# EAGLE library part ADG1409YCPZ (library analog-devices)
4 Ohm RON, 4-Channel, ±15 V/+12 V/±5 V iCMOS Multiplexers Source: 8x ADG1408_1409.pdf
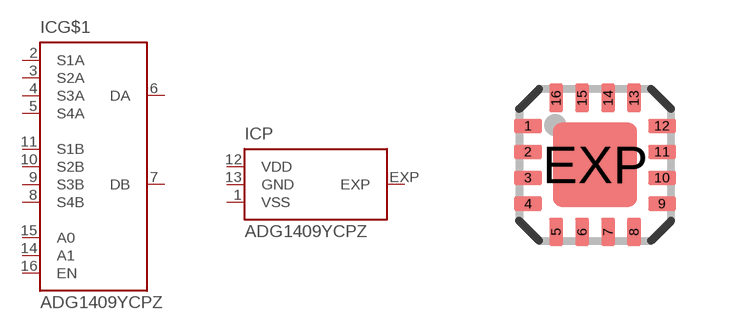
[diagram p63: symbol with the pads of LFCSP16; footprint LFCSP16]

Designator prefix IC; gates G$1=ADG1409 P=PWR-VSS_GND_VDD_EXP

## ADG1409YCPZ (MPN: ADG1409YCPZ-REEL7; OC_FARNELL: 1438941; OC_NEWARK: 46M5169)  [LFCSP16]
1  P:VSS  pwr
2  G$1:S1A
3  G$1:S2A
4  G$1:S3A
5  G$1:S4A
6  G$1:DA
7  G$1:DB
8  G$1:S4B
9  G$1:S3B
10  G$1:S2B
11  G$1:S1B
12  P:VDD  pwr
13  P:GND  pwr
14  G$1:A1  in
15  G$1:A0  in
16  G$1:EN  in
EXP  P:EXP  pas

## Footprint LFCSP16 (pad centres in mm)
16-Terminal Leadless Frame Chip Scale Package [LFCSP] (CP) Source: Analog Devices .. 780914713ADD8704_0.pdf
smd 0.7 x 0.35: 1 -1.675,0.975; 2 -1.675,0.325; 3 -1.675,-0.325; 4 -1.675,-0.975; 9 1.675,-0.975; 10 1.675,-0.325; 11 1.675,0.325; 12 1.675,0.975
smd 0.35 x 0.7: 5 -0.975,-1.675; 6 -0.325,-1.675; 7 0.325,-1.675; 8 0.975,-1.675; 13 0.975,1.675; 14 0.325,1.675; 15 -0.325,1.675; 16 -0.975,1.675
smd 2.1 x 2.1: EXP 0,0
